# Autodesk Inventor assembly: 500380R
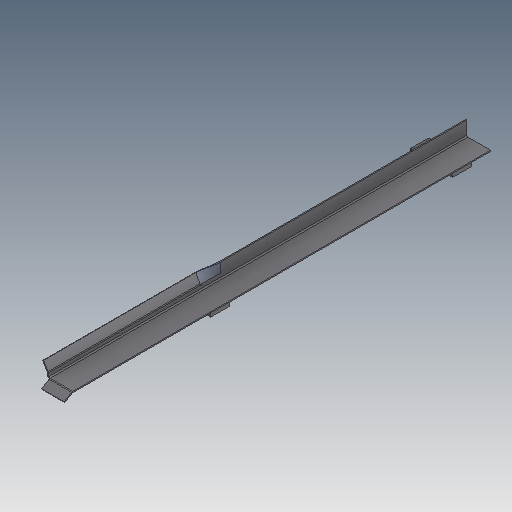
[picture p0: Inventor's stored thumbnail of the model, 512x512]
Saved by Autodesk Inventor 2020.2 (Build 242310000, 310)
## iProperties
Created: 1999-12
Part Number: 500380R
Document SubType Name: Assembly
Designer: sspink
Mass: 1184.99 g
Surface Area: 2689.76 cm^2
Volume: 450.261 cm^3
Density: 2.6318 g/cm^3
Control State: 0
Checked Out: False
Last Check In By: gpurviance
Master: False
Shininess: 0.0
Length Units: 11269
Angle Units: 11279
Time Units: 11290
Mass Units: 11283
Length Display Precision: 3
Angle Display Precision: 2
Compacted: True
Dimensions: 53,1x1139,7x114 mm
Mass: 1,185 kg
DocNumber: 500380R.iam
Folder: 01 - Themengebiete\Simplification\01 - Packaging machine\
VDS_Category: 3D Komponenten
Density: 0.0
Volumn: 0.0
Area: 0.0
PropertySet Name: Model Information
Author: sspink
Revision Number: -
Title: 500380R
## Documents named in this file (4)
- D:\07 - DEMODATEN\OTX 2019 - Dataset - UPDATE - Dez2019\Designs\07-Packing machine\500380R.iam
- D:\07 - DEMODATEN\OTX 2019 - Dataset - UPDATE - Dez2019\Designs\07-Packing machine\Parts\ADSK-011363.ipt
- D:\07 - DEMODATEN\OTX 2019 - Dataset - UPDATE - Dez2019\Designs\07-Packing machine\Parts\ADSK-011362.ipt
- D:\07 - DEMODATEN\OTX 2019 - Dataset - UPDATE - Dez2019\Designs\07-Packing machine\Parts\ADSK-011384.ipt
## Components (4 placed, 3 different names)
1. ADSK-011362:1 — Fluchtend:6, Fluchtend:1, Passend:1, Fluchtend:2, Passend:7, Passend:8, Passend:9, Passend:10
2. ADSK-011363:3 — Fluchtend:6, Fluchtend:1, Fluchtend:4
3. ADSK-011363:4 — Passend:1, Fluchtend:2, Passend:7, Fluchtend:4
4. ADSK-011384:1 — Passend:8, Passend:9, Passend:10
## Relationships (9: Mate 5, Flush 4)
- Fluchtend:6 [Flush]: ADSK-011362:1 ↔ ADSK-011363:3
- Fluchtend:1 [Flush]: ADSK-011362:1 ↔ ADSK-011363:3
- Passend:1 [Mate]: ADSK-011362:1 ↔ ADSK-011363:4
- Fluchtend:2 [Flush]: ADSK-011362:1 ↔ ADSK-011363:4
- Passend:7 [Mate]: ADSK-011362:1 ↔ ADSK-011363:4
- Fluchtend:4 [Flush]: ADSK-011363:3 ↔ ADSK-011363:4
- Passend:8 [Mate]: ADSK-011362:1 ↔ ADSK-011384:1
- Passend:9 [Mate]: ADSK-011362:1 ↔ ADSK-011384:1
- Passend:10 [Mate]: ADSK-011362:1 ↔ ADSK-011384:1
